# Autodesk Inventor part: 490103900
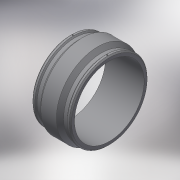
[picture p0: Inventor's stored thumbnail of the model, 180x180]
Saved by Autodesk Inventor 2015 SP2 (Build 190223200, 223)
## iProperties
Created: 2017-06
Part Number: 490103900
Material: Generic
Description: PLASSON COUPLER 900
Document SubType Name: Modeling
Designer: KIM
Mass: 96874 g
Surface Area: 34549.7 cm^2
Volume: 96874 cm^3
Density: 1 g/cm^3
Appearance: Default
Author: KIM
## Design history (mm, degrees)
derived "490103.ipt"
feature "Solid1::490103.ipt"
tag "TaggingFeature1"
body "Solid1"
other parameters: "d22" = 1006, "d24" = 975.82, "d25" = 135 deg, "d27" = 135 deg, "d29" = 503, "d35" = 15, "d39" = 0, "d40" = 4, "d41" = 14, "d42" = 0, "d43" = 135 deg, "d44" = 55, "d46" = 6, "d47" = 0, "A_" = 503, "d_2" = 12
